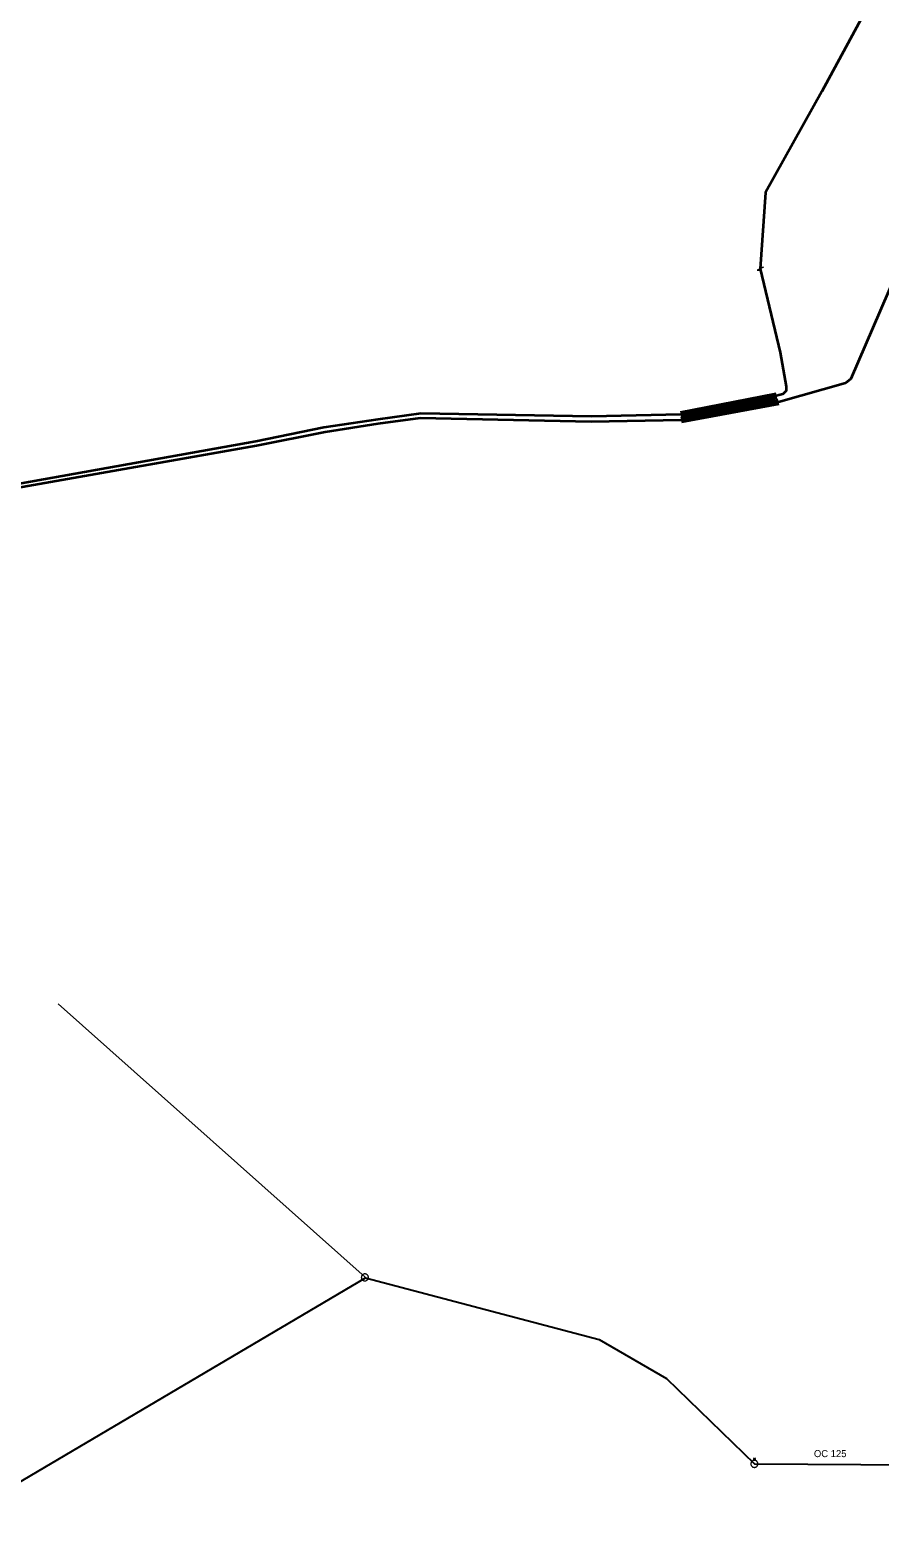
# Model space of a CAD drawing. Extents: x -659250 to -657316, y -997555 to -993684.
# Drawn here: x -658747 to -658626.7, y -994219.6 to -994006.2 of the extents above; entities that cross this region are included whole.
import ezdxf

# ---------------------------------------------------------------- set-up
doc = ezdxf.new("R2010")
doc.units = 0
doc.header["$LTSCALE"] = 0.4
doc.layers.add('1', color=7, linetype='Continuous')
for name, color, linetype, lineweight in [('13', 7, 'Continuous', 13), ('14', 7, 'Continuous', 25), ('17', 7, 'Continuous', 25), ('23', 7, 'Continuous', 13), ('3', 7, 'Continuous', 106), ('47', 7, 'Continuous', 13)]:
    doc.layers.add(name, color=color, linetype=linetype, lineweight=lineweight)

msp = doc.modelspace()

# ---------------------------------------------------------------- linework, layer by layer
at = {"layer": '13'}
msp.add_line((-658699.614, -994182.725), (-658743.091, -994143.998), dxfattribs=at)
at = {"layer": '14', "lineweight": 13}
msp.add_line((-658699.55, -994182.802), (-658699.614, -994182.725), dxfattribs=at)
at = {"layer": '17'}
msp.add_line((-658644.456, -994209.127), (-658621.638, -994209.272), dxfattribs=at)
at = {"layer": '17', "lineweight": 35}
for points in [[(-658598.399, -993989.84), (-658601.615, -993988.207), (-658617.69, -993983), (-658634.91, -994014.859), (-658642.89, -994029.14), (-658643.64, -994039.93)], [(-658606.489, -993999.12), (-658630.8, -994055.498), (-658631.567, -994056.124), (-658641.039, -994058.82), (-658654.85, -994061.37), (-658667.579, -994061.629), (-658691.82, -994061.09), (-658697.82, -994061.89), (-658705.28, -994063.05), (-658714.96, -994065.02), (-658748.18, -994070.859), (-658765.02, -994074.25), (-658773.51, -994075.829), (-658797.75, -994079.43), (-658815.379, -994082.92), (-658817.14, -994084.09), (-658829.09, -994095.52), (-658850.25, -994116.16), (-658876.489, -994141.66), (-658906.53, -994170.03)], [(-658643.64, -994039.93), (-658640.84, -994051.8), (-658639.96, -994056.609), (-658639.984, -994057.217), (-658640.443, -994057.684), (-658641, -994057.84), (-658641.35, -994057.94), (-658654.89, -994060.579), (-658667.559, -994060.85), (-658691.719, -994060.449), (-658697.8, -994061.3), (-658705.43, -994062.42), (-658715.059, -994064.41), (-658748.309, -994070.35), (-658764.879, -994073.64), (-658773.8, -994075.28), (-658797.859, -994078.789), (-658815.85, -994082.199), (-658817.64, -994083.44), (-658829.469, -994094.96), (-658850.66, -994115.71), (-658876.68, -994141.01), (-658906.859, -994169.59)]]:
    msp.add_lwpolyline(points, dxfattribs=at)
at = {"layer": '17'}
msp.add_lwpolyline([(-658966.184, -994338.363), (-658947.736, -994329.3), (-658699.55, -994182.802), (-658666.443, -994191.519), (-658656.921, -994197.046), (-658644.456, -994209.127)], dxfattribs=at)
at = {"layer": '23'}
msp.add_line((-658644.369, -994208.479), (-658644.565, -994208.479), dxfattribs=at)
for points in [[(-658699.137, -994182.742), (-658699.139, -994182.689), (-658699.149, -994182.637), (-658699.164, -994182.588), (-658699.183, -994182.539), (-658699.206, -994182.493), (-658699.237, -994182.449), (-658699.269, -994182.409), (-658699.306, -994182.373), (-658699.348, -994182.34), (-658699.392, -994182.312), (-658699.438, -994182.288), (-658699.489, -994182.27), (-658699.539, -994182.257), (-658699.59, -994182.25), (-658699.642, -994182.247), (-658699.696, -994182.251), (-658699.745, -994182.259), (-658699.798, -994182.274), (-658699.845, -994182.292), (-658699.892, -994182.316), (-658699.936, -994182.347), (-658699.975, -994182.38), (-658700.012, -994182.418), (-658700.046, -994182.458), (-658700.073, -994182.502), (-658700.095, -994182.55), (-658700.114, -994182.598), (-658700.127, -994182.649), (-658700.134, -994182.701), (-658700.137, -994182.753), (-658700.134, -994182.805), (-658700.125, -994182.857), (-658700.11, -994182.908), (-658700.092, -994182.956), (-658700.066, -994183.001), (-658700.038, -994183.045), (-658700.004, -994183.086), (-658699.967, -994183.123), (-658699.926, -994183.155)], [(-658699.798, -994182.274), (-658699.845, -994182.292), (-658699.892, -994182.316), (-658699.936, -994182.347), (-658699.975, -994182.38), (-658700.012, -994182.418), (-658700.046, -994182.458), (-658700.073, -994182.502), (-658700.095, -994182.55), (-658700.114, -994182.598), (-658700.127, -994182.649), (-658700.134, -994182.701), (-658700.137, -994182.753), (-658700.134, -994182.805), (-658700.125, -994182.857), (-658700.11, -994182.908), (-658700.092, -994182.956), (-658700.066, -994183.001), (-658700.038, -994183.045), (-658700.004, -994183.086), (-658699.967, -994183.123), (-658699.926, -994183.155), (-658699.882, -994183.183), (-658699.835, -994183.206), (-658699.786, -994183.225), (-658699.735, -994183.237), (-658699.683, -994183.244), (-658699.632, -994183.247), (-658699.58, -994183.243), (-658699.527, -994183.235), (-658699.477, -994183.221), (-658699.428, -994183.201), (-658699.382, -994183.177), (-658699.338, -994183.149), (-658699.299, -994183.114), (-658699.262, -994183.078), (-658699.23, -994183.037), (-658699.201, -994182.992), (-658699.178, -994182.945), (-658699.159, -994182.896)], [(-658699.926, -994183.155), (-658699.882, -994183.183), (-658699.835, -994183.206), (-658699.786, -994183.225), (-658699.735, -994183.237), (-658699.683, -994183.244), (-658699.632, -994183.247), (-658699.58, -994183.243), (-658699.527, -994183.235), (-658699.477, -994183.221), (-658699.428, -994183.201), (-658699.382, -994183.177), (-658699.338, -994183.149), (-658699.299, -994183.114), (-658699.262, -994183.078), (-658699.23, -994183.037), (-658699.201, -994182.992), (-658699.178, -994182.945), (-658699.159, -994182.896), (-658699.147, -994182.845), (-658699.139, -994182.794), (-658699.137, -994182.742), (-658699.139, -994182.689), (-658699.149, -994182.637), (-658699.164, -994182.588), (-658699.183, -994182.539), (-658699.206, -994182.493), (-658699.237, -994182.449), (-658699.269, -994182.409), (-658699.306, -994182.373), (-658699.348, -994182.34), (-658699.392, -994182.312), (-658699.438, -994182.288), (-658699.489, -994182.27), (-658699.539, -994182.257), (-658699.59, -994182.25), (-658699.642, -994182.247), (-658699.696, -994182.251), (-658699.745, -994182.259), (-658699.798, -994182.274)], [(-658699.159, -994182.896), (-658699.147, -994182.845), (-658699.139, -994182.794), (-658699.137, -994182.742)], [(-658643.979, -994209.144), (-658643.981, -994209.091), (-658643.99, -994209.039), (-658644.005, -994208.99), (-658644.024, -994208.941), (-658644.048, -994208.895), (-658644.078, -994208.851), (-658644.111, -994208.811), (-658644.148, -994208.775), (-658644.189, -994208.742), (-658644.233, -994208.714), (-658644.28, -994208.69), (-658644.33, -994208.672), (-658644.38, -994208.659), (-658644.431, -994208.652), (-658644.483, -994208.649), (-658644.537, -994208.653), (-658644.587, -994208.661), (-658644.639, -994208.676), (-658644.686, -994208.694), (-658644.733, -994208.718), (-658644.777, -994208.749), (-658644.817, -994208.782), (-658644.854, -994208.82), (-658644.887, -994208.86), (-658644.914, -994208.904), (-658644.937, -994208.952), (-658644.955, -994209), (-658644.968, -994209.051), (-658644.975, -994209.103), (-658644.979, -994209.155), (-658644.976, -994209.207), (-658644.967, -994209.259), (-658644.953, -994209.31), (-658644.934, -994209.358), (-658644.909, -994209.403), (-658644.88, -994209.447), (-658644.847, -994209.488), (-658644.809, -994209.525), (-658644.768, -994209.557)], [(-658644.639, -994208.676), (-658644.686, -994208.694), (-658644.733, -994208.718), (-658644.777, -994208.749), (-658644.817, -994208.782), (-658644.854, -994208.82), (-658644.887, -994208.86), (-658644.914, -994208.904), (-658644.937, -994208.952), (-658644.955, -994209), (-658644.968, -994209.051), (-658644.975, -994209.103), (-658644.979, -994209.155), (-658644.976, -994209.207), (-658644.967, -994209.259), (-658644.953, -994209.31), (-658644.934, -994209.358), (-658644.909, -994209.403), (-658644.88, -994209.447), (-658644.847, -994209.488), (-658644.809, -994209.525), (-658644.768, -994209.557), (-658644.725, -994209.585), (-658644.677, -994209.608), (-658644.629, -994209.627), (-658644.577, -994209.639), (-658644.526, -994209.646), (-658644.474, -994209.649), (-658644.422, -994209.645), (-658644.37, -994209.637), (-658644.319, -994209.623), (-658644.271, -994209.603), (-658644.224, -994209.579), (-658644.181, -994209.551), (-658644.141, -994209.516), (-658644.104, -994209.48), (-658644.072, -994209.439), (-658644.043, -994209.394), (-658644.02, -994209.347), (-658644.002, -994209.298)], [(-658644.768, -994209.557), (-658644.725, -994209.585), (-658644.677, -994209.608), (-658644.629, -994209.627), (-658644.577, -994209.639), (-658644.526, -994209.646), (-658644.474, -994209.649), (-658644.422, -994209.645), (-658644.37, -994209.637), (-658644.319, -994209.623), (-658644.271, -994209.603), (-658644.224, -994209.579), (-658644.181, -994209.551), (-658644.141, -994209.516), (-658644.104, -994209.48), (-658644.072, -994209.439), (-658644.043, -994209.394), (-658644.02, -994209.347), (-658644.002, -994209.298), (-658643.99, -994209.247), (-658643.982, -994209.196), (-658643.979, -994209.144), (-658643.981, -994209.091), (-658643.99, -994209.039), (-658644.005, -994208.99), (-658644.024, -994208.941), (-658644.048, -994208.895), (-658644.078, -994208.851), (-658644.111, -994208.811), (-658644.148, -994208.775), (-658644.189, -994208.742), (-658644.233, -994208.714), (-658644.28, -994208.69), (-658644.33, -994208.672), (-658644.38, -994208.659), (-658644.431, -994208.652), (-658644.483, -994208.649), (-658644.537, -994208.653), (-658644.587, -994208.661), (-658644.639, -994208.676)], [(-658644.565, -994208.576), (-658644.565, -994208.427), (-658644.466, -994208.276), (-658644.369, -994208.427), (-658644.369, -994208.576)], [(-658644.002, -994209.298), (-658643.99, -994209.247), (-658643.982, -994209.196), (-658643.979, -994209.144)]]:
    msp.add_lwpolyline(points, dxfattribs=at)
at = {"layer": '3'}
for p, q in [((-658641.35, -994057.94), (-658654.89, -994060.579)), ((-658641.039, -994058.82), (-658654.85, -994061.37))]:
    msp.add_line(p, q, dxfattribs=at)
at = {"layer": '3', "lineweight": 100}
for p, q in [((-658641.35, -994057.94), (-658654.89, -994060.579)), ((-658641.039, -994058.82), (-658654.85, -994061.37))]:
    msp.add_line(p, q, dxfattribs=at)
at = {"layer": '47'}
msp.add_line((-658643.175, -994039.719), (-658643.686, -994039.734), dxfattribs=at)
msp.add_lwpolyline([(-658643.175, -994039.719), (-658644.104, -994040.14), (-658643.593, -994040.125)], dxfattribs=at)

# ---------------------------------------------------------------- texts
at = {"layer": '1'}
msp.add_text('OC 125', height=1, dxfattribs=at).set_placement((-658636.041, -994208.195))

doc.saveas('drawing.dxf')
